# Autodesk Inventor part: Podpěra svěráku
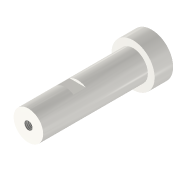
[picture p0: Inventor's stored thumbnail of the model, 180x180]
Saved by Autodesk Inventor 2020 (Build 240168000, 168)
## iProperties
Created: 2025-03
Part Number: Podpěra svěráku
Material: Ocel
Document SubType Name: Modeling
Designer: doma
Density: 7.85 g/cm^3
Appearance: Ocel
Mass: 368.146 g
Surface Area: 111.144 cm^2
Volume: 46.8976 cm^3
Author: doma
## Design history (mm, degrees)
sketch "Náčrt1"
  geometry: C1 r 17.5 at (0, 0); 1 further point
  constraints: 1 centre point, 1 coincident
  dimensions: "d0" = 35 diameter of C1
extrude "Vysunutí1" new body sketch "Náčrt1" distance "d1" = 15; taper "d2" = 0 deg
sketch "Náčrt2"
  geometry: C1 r 12 at (0, 0); 1 further point
  constraints: 1 centre point, 1 coincident
  dimensions: "d3" = 24 diameter of C1
extrude "Vysunutí2" join sketch "Náčrt2" distance "d4" = 85; taper "d5" = 0 deg
sketch "Náčrt3"
  geometry: L1 (12, 70)-(10, 70); L2 (10, 70)-(10, 60); L3 (10, 60)-(12, 60); L4 (12, 60)-(12, 70); L5 (-12, 70)-(-10, 70); L6 (-10, 70)-(-10, 60); L7 (-10, 60)-(-12, 60); L8 (-12, 60)-(-12, 70); L9 (-12, 15)-(-12, 100) reference; L10 (12, 15)-(12, 100) reference; L11 (12, 100)-(-12, 100) reference; 1 further point
  constraints: 16 end point, 5 collinear, 4 parallel, 2 horizontal, 2 perpendicular
  dimensions: "d6" = 20 distance between parallel lines of L2 L6; "d7" = 30 distance between parallel lines of L5 L11; "d8" = 10 distance of L7.end L5.start
extrude "Vysunutí3" cut sketch "Náčrt3" stored distance "d9" = 80; taper "d10" = 0 deg
sketch "Náčrt4"
  geometry: 2 further points
hole "Díra1" sketch "Náčrt4" at (0, 0) diameter "d11" = 6.647; stored, may be unused: countersink angle "d15" = 90 deg, drill point angle "d17" = 118 deg; dims "d12" = 15, "d13" = 4, "d14" = 2, "d16" = 20
sketch "Náčrt5"
  geometry: 2 further points
hole "Díra2" sketch "Náčrt5" at (0, 0) diameter "d18" = 10.106; stored, may be unused: countersink angle "d22" = 90 deg, drill point angle "d24" = 118 deg; dims "d19" = 25, "d20" = 4, "d21" = 2, "d23" = 32
node "Těleso1"
